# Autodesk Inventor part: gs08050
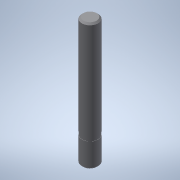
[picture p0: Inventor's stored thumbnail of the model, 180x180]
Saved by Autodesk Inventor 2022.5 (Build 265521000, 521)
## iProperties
Created: 2016-12
Part Number: gs08050
Material: 一般
Document SubType Name: Modeling
Designer: imaocorp
Density: 1 g/cm^3
Appearance: 既定
Author: imaocorp
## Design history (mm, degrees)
node "gs08050.x_t1"
node "gs08050"
node "Base1"
